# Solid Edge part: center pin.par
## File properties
Author: Binay
Template: sync ansi part.par
Last saved by: CADCIM
Revision: 13
Application: Solid Edge
Accuracy: 0.990
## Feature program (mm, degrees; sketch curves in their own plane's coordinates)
sketch for "unnamed Hole 1" plane through (42.6694, 3.8175, 49.1782) normal (0, 0, 1) x-axis (1, 0, 0)
  hole centre (0.7149, -3.8175) bore radius 8.001
hole "unnamed Hole 1" through
pattern "unnamed Pattern 1" of "unnamed Hole 1"
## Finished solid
Body 1: solid body, 7 faces, 7 edges, 0 vertices.
  Faces by surface: cylinder 3, plane 3, cone 1
  Edges by curve: circle 7
Bounding box of the edges (mm): 34.290 x 34.290 x 76.200, from (26.2393, -17.145, -27.0218) to (60.5293, 17.145, 49.1782).
Cylindrical faces by radius (mm): R8.001 x1, R12.7 x1, R17.145 x1
Conical faces (half-angle, radius in mm at the cone's reference point): 45 deg R11.176 x1
Planar faces by outward normal: +z 1, -z 2
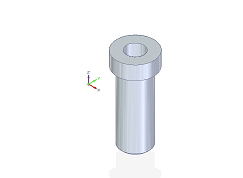
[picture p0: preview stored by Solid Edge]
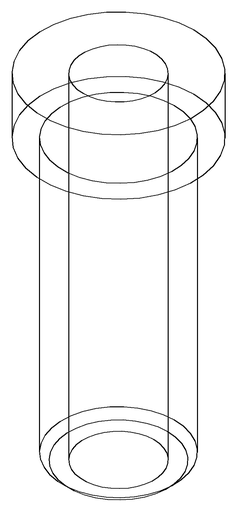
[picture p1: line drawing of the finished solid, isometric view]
